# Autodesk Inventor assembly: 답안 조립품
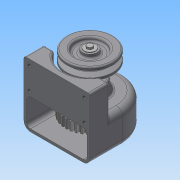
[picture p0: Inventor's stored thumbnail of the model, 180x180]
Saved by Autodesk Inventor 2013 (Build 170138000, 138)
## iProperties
Created: 2015-03
Part Number: 답안 조립품
Document SubType Name: Assembly
Designer: Administrator
Author: Administrator
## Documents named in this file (14)
- C:\Documents and Settings\Administrator\바탕 화면\450214V1003\답안 조립품.iam
- C:\Documents and Settings\Administrator\바탕 화면\450214V1003\1-본체.ipt
- C:\Documents and Settings\Administrator\바탕 화면\450214V1003\베어링 6001.ipt
- C:\Documents and Settings\Administrator\바탕 화면\450214V1003\축.ipt
- C:\Documents and Settings\Administrator\바탕 화면\450214V1003\5-스퍼기어.ipt
- C:\Documents and Settings\Administrator\바탕 화면\450214V1003\키5x5.ipt
- C:\Documents and Settings\Administrator\바탕 화면\450214V1003\축커버.ipt
- C:\Documents and Settings\Administrator\바탕 화면\450214V1003\키4x4.ipt
- C:\Documents and Settings\Administrator\바탕 화면\450214V1003\오일실.ipt
- C:\Documents and Settings\Administrator\바탕 화면\450214V1003\M3x0.5.ipt
- C:\Documents and Settings\Administrator\바탕 화면\450214V1003\4-V벨트풀리.ipt
- C:\Documents and Settings\Administrator\바탕 화면\450214V1003\와샤.ipt
- C:\Documents and Settings\Administrator\바탕 화면\450214V1003\M5x0.8.ipt
- M5x0.8.ipt
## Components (7 placed, 4 different names)
1. 1-본체:1
2. 4-V벨트풀리:1 — 각도:4, 플러쉬:1
3. M5x0.8:1 — 각도:5
4. M3x0.5:1
5. M3x0.5:2
6. M3x0.5:3
7. M3x0.5:4
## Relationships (3: Angle 2, Flush 1)
- 각도:4 [Angle]: 4-V벨트풀리:1
- 플러쉬:1 [Flush]: 4-V벨트풀리:1
- 각도:5 [Angle]: M5x0.8:1
